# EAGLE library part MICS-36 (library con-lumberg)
CONNECTOR
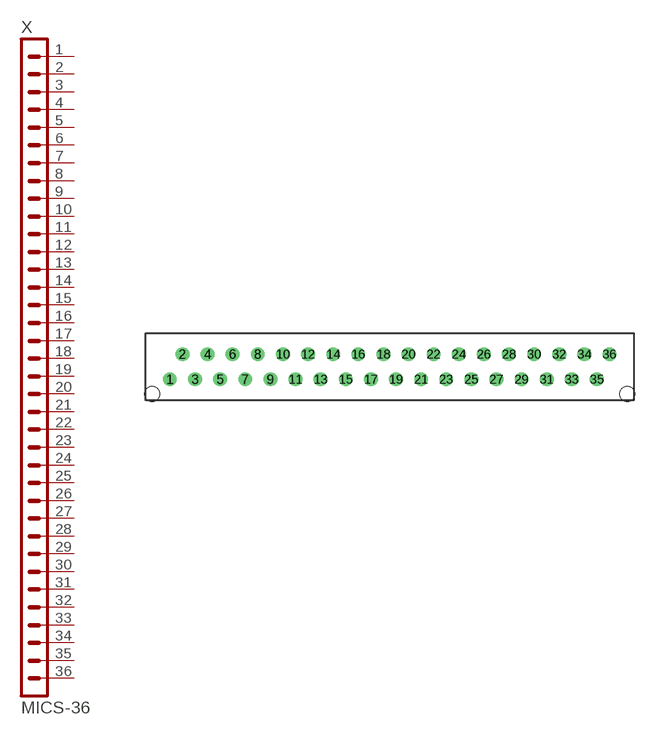
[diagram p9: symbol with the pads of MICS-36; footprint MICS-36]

Designator prefix X

## MICS-36 (OC_FARNELL: 871266; OC_NEWARK: unknown)  [MICS-36]
1  1  pas
2  2  pas
3  3  pas
4  4  pas
5  5  pas
6  6  pas
7  7  pas
8  8  pas
9  9  pas
10  10  pas
11  11  pas
12  12  pas
13  13  pas
14  14  pas
15  15  pas
16  16  pas
17  17  pas
18  18  pas
19  19  pas
20  20  pas
21  21  pas
22  22  pas
23  23  pas
24  24  pas
25  25  pas
26  26  pas
27  27  pas
28  28  pas
29  29  pas
30  30  pas
31  31  pas
32  32  pas
33  33  pas
34  34  pas
35  35  pas
36  36  pas

## Footprint MICS-36 (pad centres in mm)
CONNECTOR
drill 0.85 pad 1.397 round: 1 -22.225,-1.27; 2 -20.955,1.27; 3 -19.685,-1.27; 4 -18.415,1.27; 5 -17.145,-1.27; 6 -15.875,1.27; 7 -14.605,-1.27; 8 -13.335,1.27; 9 -12.065,-1.27; 10 -10.795,1.27; 11 -9.525,-1.27; 12 -8.255,1.27; 13 -6.985,-1.27; 14 -5.715,1.27; 15 -4.445,-1.27; 16 -3.175,1.27; 17 -1.905,-1.27; 18 -0.635,1.27; 19 0.635,-1.27; 20 1.905,1.27; 21 3.175,-1.27; 22 4.445,1.27; 23 5.715,-1.27; 24 6.985,1.27; 25 8.255,-1.27; 26 9.525,1.27; 27 10.795,-1.27; 28 12.065,1.27; 29 13.335,-1.27; 30 14.605,1.27; 31 15.875,-1.27; 32 17.145,1.27; 33 18.415,-1.27; 34 19.685,1.27; 35 20.955,-1.27; 36 22.225,1.27
hole 1.5 at 24.025,-2.75
hole 1.5 at -24.025,-2.75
